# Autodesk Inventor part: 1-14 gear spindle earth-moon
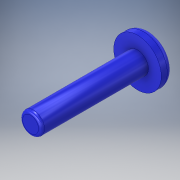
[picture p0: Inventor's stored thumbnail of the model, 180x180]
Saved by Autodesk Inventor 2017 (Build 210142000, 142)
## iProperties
Created: 2017-04
Part Number: 1-14 gear spindle earth-moon
Material: Generic
Document SubType Name: Modeling
Designer: Stan
Density: 1 g/cm^3
Appearance: Blue - Wall Paint - Glossy
Author: Stan
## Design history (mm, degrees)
sketch "Sketch1"
  geometry: C1 r 6.35 at (0, 0); 1 further point
  constraints: 1 centre point, 1 coincident
  dimensions: "d0" = 12.7 diameter of C1
extrude "Extrusion1" new body sketch "Sketch1" distance "d1" = 3.175; taper "d2" = 0 deg
sketch "Sketch2"
  geometry: C1 r 2.921 at (0, 0); 1 further point
  constraints: 1 centre point, 1 coincident
  dimensions: "d3" = 5.842 diameter of C1
extrude "Extrusion2" join sketch "Sketch2" distance "d4" = 28.575; taper "d5" = 0 deg
fillet "Fillet1" dims "d6" = 1.5875
fillet "Fillet2" dims "d7" = 0.79375
body "Solid1"
